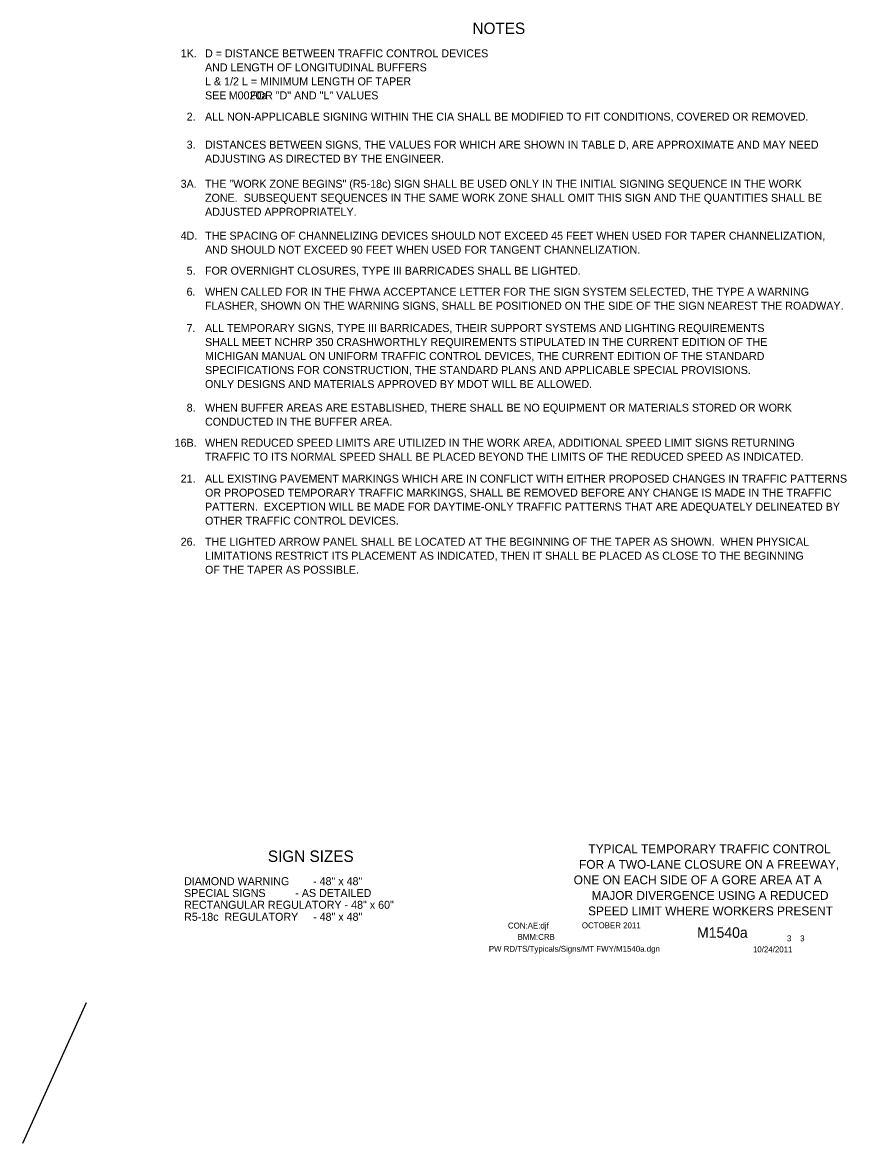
# Model space of a CAD drawing. Extents: x 16452 to 19504, y 5713 to 7079.
# Drawn here: x 18639 to 19504, y 5732 to 6909 of the extents above; entities that cross this region are included whole.
import ezdxf

# ---------------------------------------------------------------- set-up
doc = ezdxf.new("R2010")
doc.units = 0
for name, color, linetype in [('BORDER', 7, 'Continuous'), ('BORDER_SIGNAL_WO', 7, 'Continuous'), ('TYPICAL_TEXT_DIMEN_PR', 7, 'Continuous')]:
    doc.layers.add(name, color=color, linetype=linetype)

msp = doc.modelspace()

# ---------------------------------------------------------------- linework, layer by layer
at = {"layer": 'TYPICAL_TEXT_DIMEN_PR'}
msp.add_line((18705.8, 5880), (18639, 5732.4), dxfattribs=at)

# ---------------------------------------------------------------- texts
at = {"layer": 'BORDER'}
for s, p in [('TYPICAL TEMPORARY TRAFFIC CONTROL', (19233.2, 6037.1)), ('FOR A TWO-LANE CLOSURE ON A FREEWAY,', (19223.4, 6020.8)), ('ONE ON EACH SIDE OF A GORE AREA AT A ', (19217.7, 6004.5)), ('MAJOR DIVERGENCE USING A REDUCED', (19236.5, 5988.2)), ('SPEED LIMIT WHERE WORKERS PRESENT', (19232.9, 5971.9))]:
    msp.add_text(s, height=9.3, dxfattribs=at).set_placement(p)
at = {"layer": 'BORDER_SIGNAL_WO'}
for s, height, p in [('CON:AE:djf  ', 6.2, (19148.7, 5958.1)), ('    OCTOBER 2011    ', 6.2, (19217.1, 5958.3)), ('    M1540a   ', 11, (19330.9, 5948.4)), ('BMM:CRB   ', 6.2, (19158.8, 5946.2)), (' 3    3 ', 6.2, (19439.4, 5944.7)), ('PW RD/TS/Typicals/Signs/MT FWY/M1540a.dgn      ', 6.2, (19128.6, 5933.7)), ('10/24/2011    ', 6.2, (19405.9, 5933.1))]:
    msp.add_text(s, height=height, dxfattribs=at).set_placement(p)
at = {"layer": 'TYPICAL_TEXT_DIMEN_PR'}
for s, height, p in [('NOTES', 12, (19111.5, 6897)), ('1K.', 8.4, (18805.2, 6872.5)), ('D = DISTANCE BETWEEN TRAFFIC CONTROL DEVICES', 8.4, (18830.7, 6872.5)), ('AND LENGTH OF LONGITUDINAL BUFFERS', 8.4, (18830.7, 6857.8)), ('L & 1/2 L = MINIMUM LENGTH OF TAPER', 8.4, (18830.7, 6843.1)), ('SEE        FOR "D" AND "L" VALUES', 8.4, (18830.7, 6828.4)), ('M0020a', 8.4, (18855.6, 6828.4)), ('2.', 8.4, (18811.4, 6806.1)), ('ALL NON-APPLICABLE SIGNING WITHIN THE CIA SHALL BE MODIFIED TO FIT CONDITIONS, COVERED OR REMOVED.', 8.4, (18830.7, 6806.1)), ('3.', 8.4, (18811.4, 6776.7)), ('DISTANCES BETWEEN SIGNS, THE VALUES FOR WHICH ARE SHOWN IN TABLE D, ARE APPROXIMATE AND MAY NEED', 8.4, (18830.7, 6776.7)), ('ADJUSTING AS DIRECTED BY THE ENGINEER.', 8.4, (18830.7, 6762)), ('3A.', 8.4, (18805.1, 6735.6)), ('THE "WORK ZONE BEGINS" (R5-18c) SIGN SHALL BE USED ONLY IN THE INITIAL SIGNING SEQUENCE IN THE WORK', 8.4, (18830.7, 6735.6)), ('ZONE.  SUBSEQUENT SEQUENCES IN THE SAME WORK ZONE SHALL OMIT THIS SIGN AND THE QUANTITIES SHALL BE', 8.4, (18830.7, 6720.9)), ('ADJUSTED APPROPRIATELY.', 8.4, (18830.7, 6706.2)), ('4D.', 8.4, (18805.1, 6681.2)), ('THE SPACING OF CHANNELIZING DEVICES SHOULD NOT EXCEED 45 FEET WHEN USED FOR TAPER CHANNELIZATION,', 8.4, (18830.8, 6681.1)), ('AND SHOULD NOT EXCEED 90 FEET WHEN USED FOR TANGENT CHANNELIZATION.', 8.4, (18830.8, 6666.4)), ('5.', 8.4, (18811.4, 6644.4)), ('FOR OVERNIGHT CLOSURES, TYPE III BARRICADES SHALL BE LIGHTED.', 8.4, (18830.7, 6644.4)), ('6.', 8.4, (18811.3, 6622.3)), ('WHEN CALLED FOR IN THE FHWA ACCEPTANCE LETTER FOR THE SIGN SYSTEM SELECTED, THE TYPE A WARNING ', 8.4, (18830.7, 6622.3)), ('FLASHER, SHOWN ON THE WARNING SIGNS, SHALL BE POSITIONED ON THE SIDE OF THE SIGN NEAREST THE ROADWAY.', 8.4, (18830.7, 6607.6)), ('7.', 8.4, (18811.3, 6584.2)), ('ALL TEMPORARY SIGNS, TYPE III BARRICADES, THEIR SUPPORT SYSTEMS AND LIGHTING REQUIREMENTS', 8.4, (18830.7, 6584.2)), ('SHALL MEET NCHRP 350 CRASHWORTHLY REQUIREMENTS STIPULATED IN THE CURRENT EDITION OF THE', 8.4, (18830.7, 6569.5)), ('MICHIGAN MANUAL ON UNIFORM TRAFFIC CONTROL DEVICES, THE CURRENT EDITION OF THE STANDARD', 8.4, (18830.7, 6554.8)), ('SPECIFICATIONS FOR CONSTRUCTION, THE STANDARD PLANS AND APPLICABLE SPECIAL PROVISIONS.', 8.4, (18830.7, 6540.1)), ('ONLY DESIGNS AND MATERIALS APPROVED BY MDOT WILL BE ALLOWED.', 8.4, (18830.7, 6525.4)), ('8.', 8.4, (18811.4, 6500.6)), ('WHEN BUFFER AREAS ARE ESTABLISHED, THERE SHALL BE NO EQUIPMENT OR MATERIALS STORED OR WORK     ', 8.4, (18830.7, 6500.6)), ('CONDUCTED IN THE BUFFER AREA.', 8.4, (18830.7, 6485.9)), ('16B.', 8.4, (18798.8, 6463.8)), ('WHEN REDUCED SPEED LIMITS ARE UTILIZED IN THE WORK AREA, ADDITIONAL SPEED LIMIT SIGNS RETURNING', 8.4, (18830.7, 6463.8)), ('TRAFFIC TO ITS NORMAL SPEED SHALL BE PLACED BEYOND THE LIMITS OF THE REDUCED SPEED AS INDICATED.', 8.4, (18830.7, 6449.1)), ('21.', 8.4, (18805.1, 6426.1)), ('ALL EXISTING PAVEMENT MARKINGS WHICH ARE IN CONFLICT WITH EITHER PROPOSED CHANGES IN TRAFFIC PATTERNS', 8.4, (18830.7, 6426.1)), ('OR PROPOSED TEMPORARY TRAFFIC MARKINGS, SHALL BE REMOVED BEFORE ANY CHANGE IS MADE IN THE TRAFFIC', 8.4, (18830.7, 6411.4)), ('PATTERN.  EXCEPTION WILL BE MADE FOR DAYTIME-ONLY TRAFFIC PATTERNS THAT ARE ADEQUATELY DELINEATED BY', 8.4, (18830.7, 6396.7)), ('OTHER TRAFFIC CONTROL DEVICES.', 8.4, (18830.7, 6382)), ('26.', 8.4, (18805.1, 6359.9)), ('THE LIGHTED ARROW PANEL SHALL BE LOCATED AT THE BEGINNING OF THE TAPER AS SHOWN.  WHEN PHYSICAL', 8.4, (18830.7, 6359.9)), ('LIMITATIONS RESTRICT ITS PLACEMENT AS INDICATED, THEN IT SHALL BE PLACED AS CLOSE TO THE BEGINNING', 8.4, (18830.7, 6345.2)), ('OF THE TAPER AS POSSIBLE.', 8.4, (18830.7, 6330.5)), ('SIGN SIZES', 12, (18896.7, 6028)), ('DIAMOND WARNING        - 48" x 48"', 8.4, (18808.7, 6003.6)), ('SPECIAL SIGNS          - AS DETAILED', 8.4, (18808.7, 5991.2)), ('RECTANGULAR REGULATORY - 48" x 60"', 8.4, (18808.7, 5978.8)), ('R5-18c  REGULATORY     - 48" x 48"', 8.4, (18808.7, 5966.2))]:
    msp.add_text(s, height=height, dxfattribs=at).set_placement(p)

doc.saveas('drawing.dxf')
